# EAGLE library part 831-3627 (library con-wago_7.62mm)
Serie 831, Stiftleiste (für Leiterplatten) mit abgewinkelten Einlötstiften / Series 831, Male header (for PCBs) with angled solder pins Polzahl / Pole No.: 7 Bemessungsspannung / Rated Voltage: 630 V Nennstrom / Nominal Current: 41 A Lötstiftlänge: / Solder Pin Length: 4 mm Farbe / Color: lichtgrau / light gray Stand: 01.01.2012. Die jeweils aktuellen Daten zu diesem Artikel finden Sie in unserem Produktkatalog, den Sie unter www.wago.com einsehen können. As of: 01/01/2012. Please find the newest data for this article in our product catalogue, which can be viewed under www.wago.com.
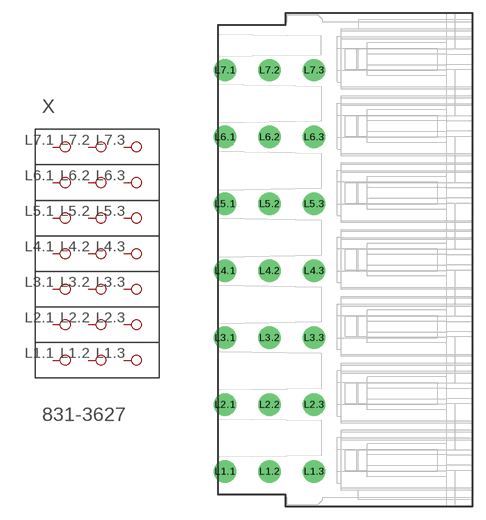
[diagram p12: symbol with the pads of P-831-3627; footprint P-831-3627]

Designator prefix X

## 831-3627  [P-831-3627]
L1.1  P1.1
L1.2  P1.2
L1.3  P1.3
L2.1  P2.1
L2.2  P2.2
L2.3  P2.3
L3.1  P3.1
L3.2  P3.2
L3.3  P3.3
L4.1  P4.1
L4.2  P4.2
L4.3  P4.3
L5.1  P5.1
L5.2  P5.2
L5.3  P5.3
L6.1  P6.1
L6.2  P6.2
L6.3  P6.3
L7.1  P7.1
L7.2  P7.2
L7.3  P7.3

## Footprint P-831-3627 (pad centres in mm)
drill 1.7 round: L1.1 -13.7,-24.13; L1.2 -8.62,-24.13; L1.3 -3.54,-24.13; L2.1 -13.7,-16.51; L2.2 -8.62,-16.51; L2.3 -3.54,-16.51; L3.1 -13.7,-8.89; L3.2 -8.62,-8.89; L3.3 -3.54,-8.89; L4.1 -13.7,-1.25; L4.2 -8.62,-1.25; L4.3 -3.54,-1.25; L5.1 -13.7,6.37; L5.2 -8.62,6.37; L5.3 -3.54,6.37; L6.1 -13.7,13.99; L6.2 -8.62,13.99; L6.3 -3.54,13.99; L7.1 -13.7,21.61; L7.2 -8.62,21.61; L7.3 -3.54,21.61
